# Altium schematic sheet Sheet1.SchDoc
size 635 x 254 mm; SheetNumber: 1; SheetTotal: 1
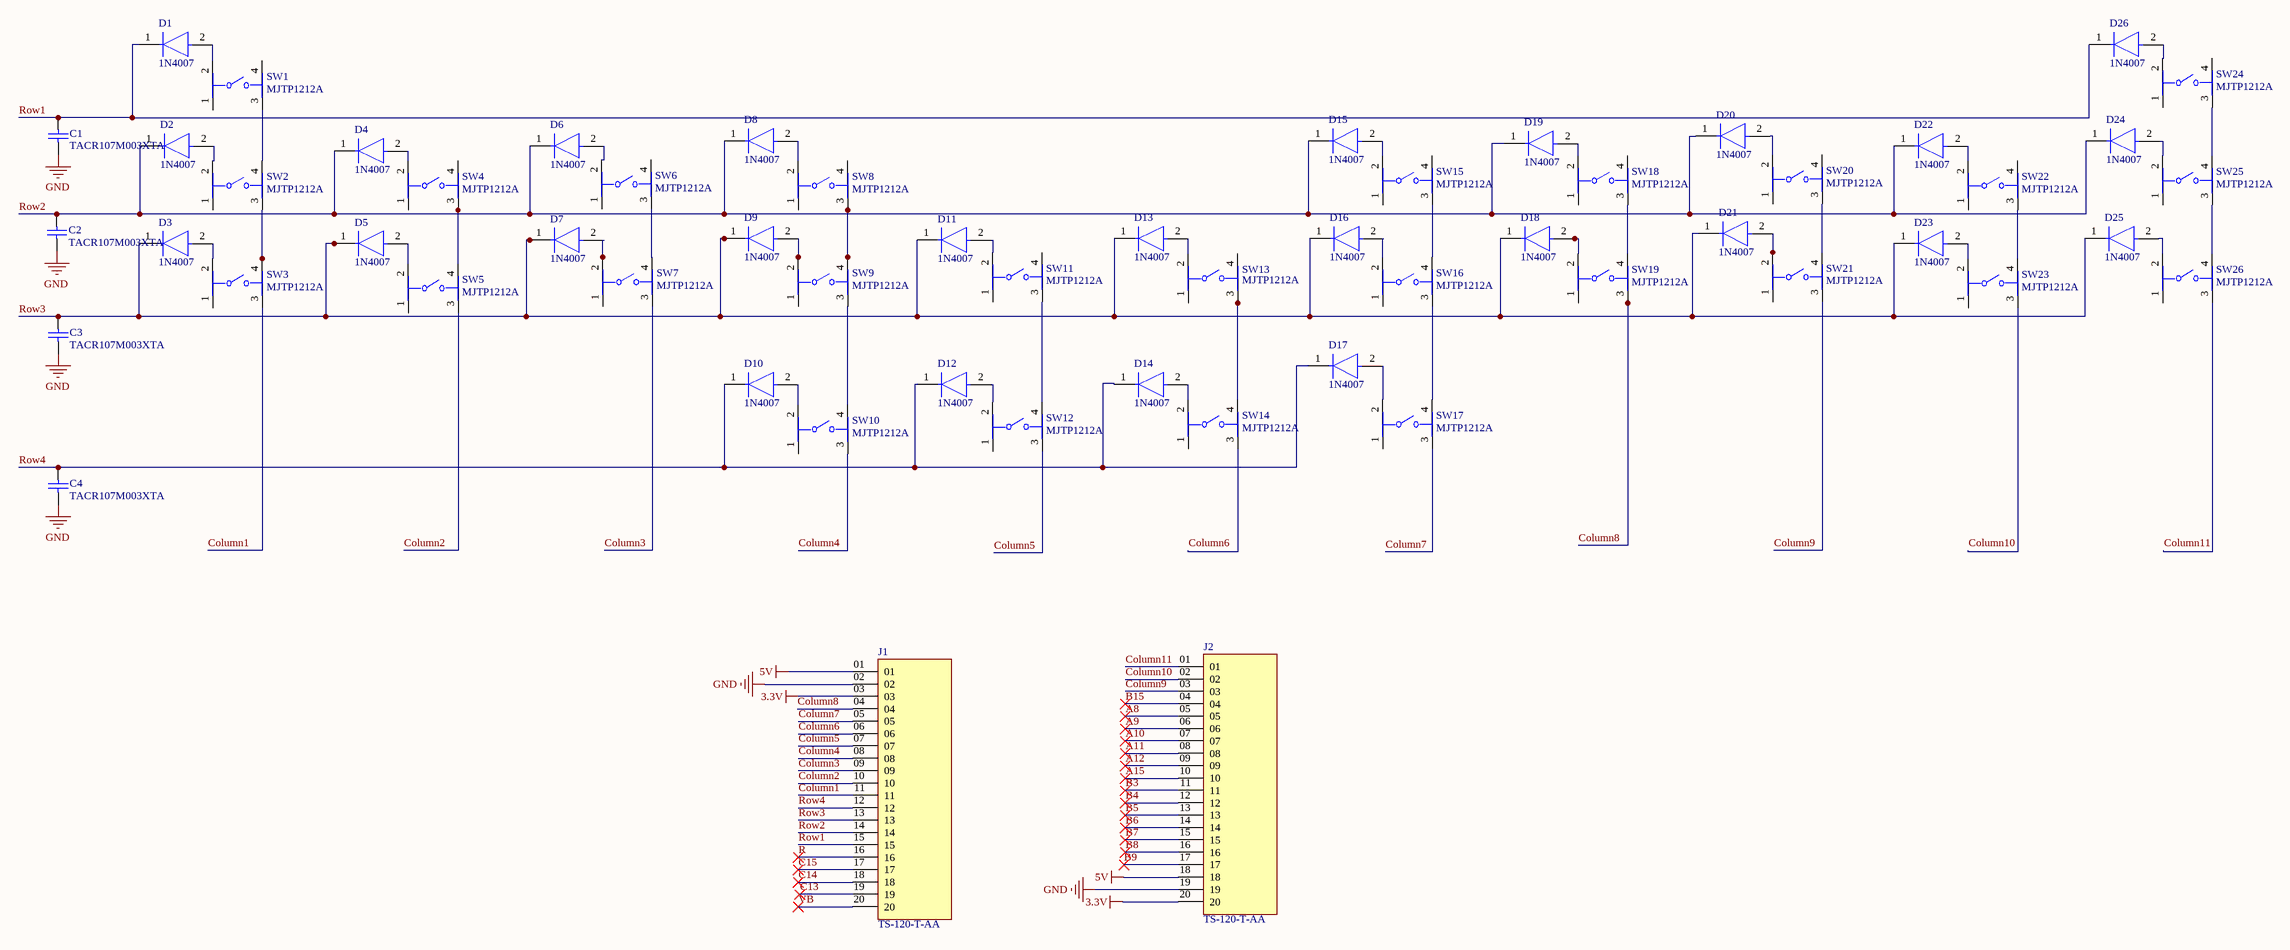
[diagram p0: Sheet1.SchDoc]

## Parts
C1  TACR107M003XTA  [CAPC2014X150X70ML20]
C2  TACR107M003XTA  [CAPC2014X150X70ML20]
C3  TACR107M003XTA  [CAPC2014X150X70ML20]
C4  TACR107M003XTA  [CAPC2014X150X70ML20]
D1  1N4007  [FP-1N4007-MFG]
D2  1N4007  [FP-1N4007-MFG]
D3  1N4007  [FP-1N4007-MFG]
D4  1N4007  [FP-1N4007-MFG]
D5  1N4007  [FP-1N4007-MFG]
D6  1N4007  [FP-1N4007-MFG]
D7  1N4007  [FP-1N4007-MFG]
D8  1N4007  [FP-1N4007-MFG]
D9  1N4007  [FP-1N4007-MFG]
D10  1N4007  [FP-1N4007-MFG]
D11  1N4007  [FP-1N4007-MFG]
D12  1N4007  [FP-1N4007-MFG]
D13  1N4007  [FP-1N4007-MFG]
D14  1N4007  [FP-1N4007-MFG]
D15  1N4007  [FP-1N4007-MFG]
D16  1N4007  [FP-1N4007-MFG]
D17  1N4007  [FP-1N4007-MFG]
D18  1N4007  [FP-1N4007-MFG]
D19  1N4007  [FP-1N4007-MFG]
D20  1N4007  [FP-1N4007-MFG]
D21  1N4007  [FP-1N4007-MFG]
D22  1N4007  [FP-1N4007-MFG]
D23  1N4007  [FP-1N4007-MFG]
D24  1N4007  [FP-1N4007-MFG]
D25  1N4007  [FP-1N4007-MFG]
D26  1N4007  [FP-1N4007-MFG]
J1  TS-120-T-AA  [SAMTEC_TS-120-T-AA]
J2  TS-120-T-AA  [SAMTEC_TS-120-T-AA]
SW1  MJTP1212A  [FP-MJTP1212A-MFG]
SW2  MJTP1212A  [FP-MJTP1212A-MFG]
SW3  MJTP1212A  [FP-MJTP1212A-MFG]
SW4  MJTP1212A  [FP-MJTP1212A-MFG]
SW5  MJTP1212A  [FP-MJTP1212A-MFG]
SW6  MJTP1212A  [FP-MJTP1212A-MFG]
SW7  MJTP1212A  [FP-MJTP1212A-MFG]
SW8  MJTP1212A  [FP-MJTP1212A-MFG]
SW9  MJTP1212A  [FP-MJTP1212A-MFG]
SW10  MJTP1212A  [FP-MJTP1212A-MFG]
SW11  MJTP1212A  [FP-MJTP1212A-MFG]
SW12  MJTP1212A  [FP-MJTP1212A-MFG]
SW13  MJTP1212A  [FP-MJTP1212A-MFG]
SW14  MJTP1212A  [FP-MJTP1212A-MFG]
SW15  MJTP1212A  [FP-MJTP1212A-MFG]
SW16  MJTP1212A  [FP-MJTP1212A-MFG]
SW17  MJTP1212A  [FP-MJTP1212A-MFG]
SW18  MJTP1212A  [FP-MJTP1212A-MFG]
SW19  MJTP1212A  [FP-MJTP1212A-MFG]
SW20  MJTP1212A  [FP-MJTP1212A-MFG]
SW21  MJTP1212A  [FP-MJTP1212A-MFG]
SW22  MJTP1212A  [FP-MJTP1212A-MFG]
SW23  MJTP1212A  [FP-MJTP1212A-MFG]
SW24  MJTP1212A  [FP-MJTP1212A-MFG]
SW25  MJTP1212A  [FP-MJTP1212A-MFG]
SW26  MJTP1212A  [FP-MJTP1212A-MFG]

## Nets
3.3V: J1.03 J2.20
5V: J1.01 J2.18
GND: C1.1 C2.1 C3.1 C4.1 J1.02 J2.19
A8: J2.05
A9: J2.06
A10: J2.07
A11: J2.08
A12: J2.09
A15: J2.10
B3: J2.11
B4: J2.12
B5: J2.13
B6: J2.14
B7: J2.15
B8: J2.16
B9: J2.17
B15: J2.04
C13: J1.19
C14: J1.18
C15: J1.17
Column1: J1.11 SW3.3
Column2: J1.10 SW5.3
Column3: J1.09 SW7.3
Column4: J1.08 SW10.3
Column5: J1.07 SW12.3
Column6: J1.06 SW14.3
Column7: J1.05 SW17.3
Column8: J1.04 SW19.3
Column9: J2.03 SW21.3
Column10: J2.02 SW23.3
Column11: J2.01 SW26.3
R: J1.16
Row1: C1.2 D1.1(C) D26.1(C) J1.15
Row2: C2.2 D2.1(C) D4.1(C) D6.1(C) D8.1(C) D15.1(C) D19.1(C) D20.1(C) D22.1(C) D24.1(C) J1.14
Row3: C3.2 D3.1(C) D5.1(C) D7.1(C) D9.1(C) D11.1(C) D13.1(C) D16.1(C) D18.1(C) D21.1(C) D23.1(C) D25.1(C) J1.13
Row4: C4.2 D10.1(C) D12.1(C) D14.1(C) D17.1(C) J1.12
VB: J1.20
NetD1_2: D1.2(A) SW1.2
NetD2_2: D2.2(A) SW2.2
NetD3_2: D3.2(A) SW3.2
NetD4_2: D4.2(A) SW4.2
NetD5_2: D5.2(A) SW5.2
NetD6_2: D6.2(A) SW6.2
NetD7_2: D7.2(A) SW7.2
NetD8_2: D8.2(A) SW8.2
NetD9_2: D9.2(A) SW9.2
NetD10_2: D10.2(A) SW10.2
NetD11_2: D11.2(A) SW11.2
NetD12_2: D12.2(A) SW12.2
NetD13_2: D13.2(A) SW13.2
NetD14_2: D14.2(A) SW14.2
NetD15_2: D15.2(A) SW15.2
NetD16_2: D16.2(A) SW16.2
NetD17_2: D17.2(A) SW17.2
NetD18_2: D18.2(A) SW19.2
NetD19_2: D19.2(A) SW18.2
NetD20_2: D20.2(A) SW20.2
NetD21_2: D21.2(A) SW21.2
NetD22_2: D22.2(A) SW22.2
NetD23_2: D23.2(A) SW23.2
NetD24_2: D24.2(A) SW25.2
NetD25_2: D25.2(A) SW26.2
NetD26_2: D26.2(A) SW24.2
NetSW1_3: SW1.3 SW2.4
NetSW2_3: SW2.3 SW3.4
NetSW4_3: SW4.3 SW5.4
NetSW6_3: SW6.3 SW7.4
NetSW8_3: SW8.3 SW9.4
NetSW9_3: SW9.3 SW10.4
NetSW11_3: SW11.3 SW12.4
NetSW13_3: SW13.3 SW14.4
NetSW15_3: SW15.3 SW16.4
NetSW16_3: SW16.3 SW17.4
NetSW18_3: SW18.3 SW19.4
NetSW20_3: SW20.3 SW21.4
NetSW22_3: SW22.3 SW23.4
NetSW24_3: SW24.3 SW25.4
NetSW25_3: SW25.3 SW26.4

Not connected (* = marked no-connect by the designer): SW1 1 4; SW2 1; SW3 1; SW4 1 4; SW5 1; SW6 1 4; SW7 1; SW8 1 4; SW9 1; SW10 1; SW11 1 4; SW12 1; SW13 1 4; SW14 1; SW15 1 4; SW16 1; SW17 1; SW18 1 4; SW19 1; SW20 1 4; SW21 1; SW22 1 4; SW23 1; SW24 1 4; SW25 1; SW26 1

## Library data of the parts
C1-C4 = CMP-2007-00028-1: Manufacturer: AVX Interconnect / Elco
D1-D26 = CMP-123542-000001-1: Rectifier diode 1000 V 1 A DO-41, ,; Manufacturer: Diotec; Max Surge Forward Current: 27A; Forward Current: 1A; Max Junction Temp: +175°C; Reverse Voltage: 1000V; Value: 15pF; Peak Reverse Current: 5uA
J1 J2 = TS-120-T-AA: Headers & Wire Housings .100 Single Row Screw Machine Terminal Strip; MF: Samtec
SW1-SW26 = CMP-47024-000003-1: SWITCH TACTILE SPST-NO 0.05A 12V; Contact Resistance: 100mR; Operating Force: 160gf; Mechanical Life: 100000Cycles; Actuator Length: 3.5mm; Throw Configuration: SPST; Illumination Type: Non-Illuminated; Actuator Material: Polyoxymethylene; Actuator Type: Standard; Switch Travel: 0.3mm; Current Rating: 50mA; Switch Function: Off-Mom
